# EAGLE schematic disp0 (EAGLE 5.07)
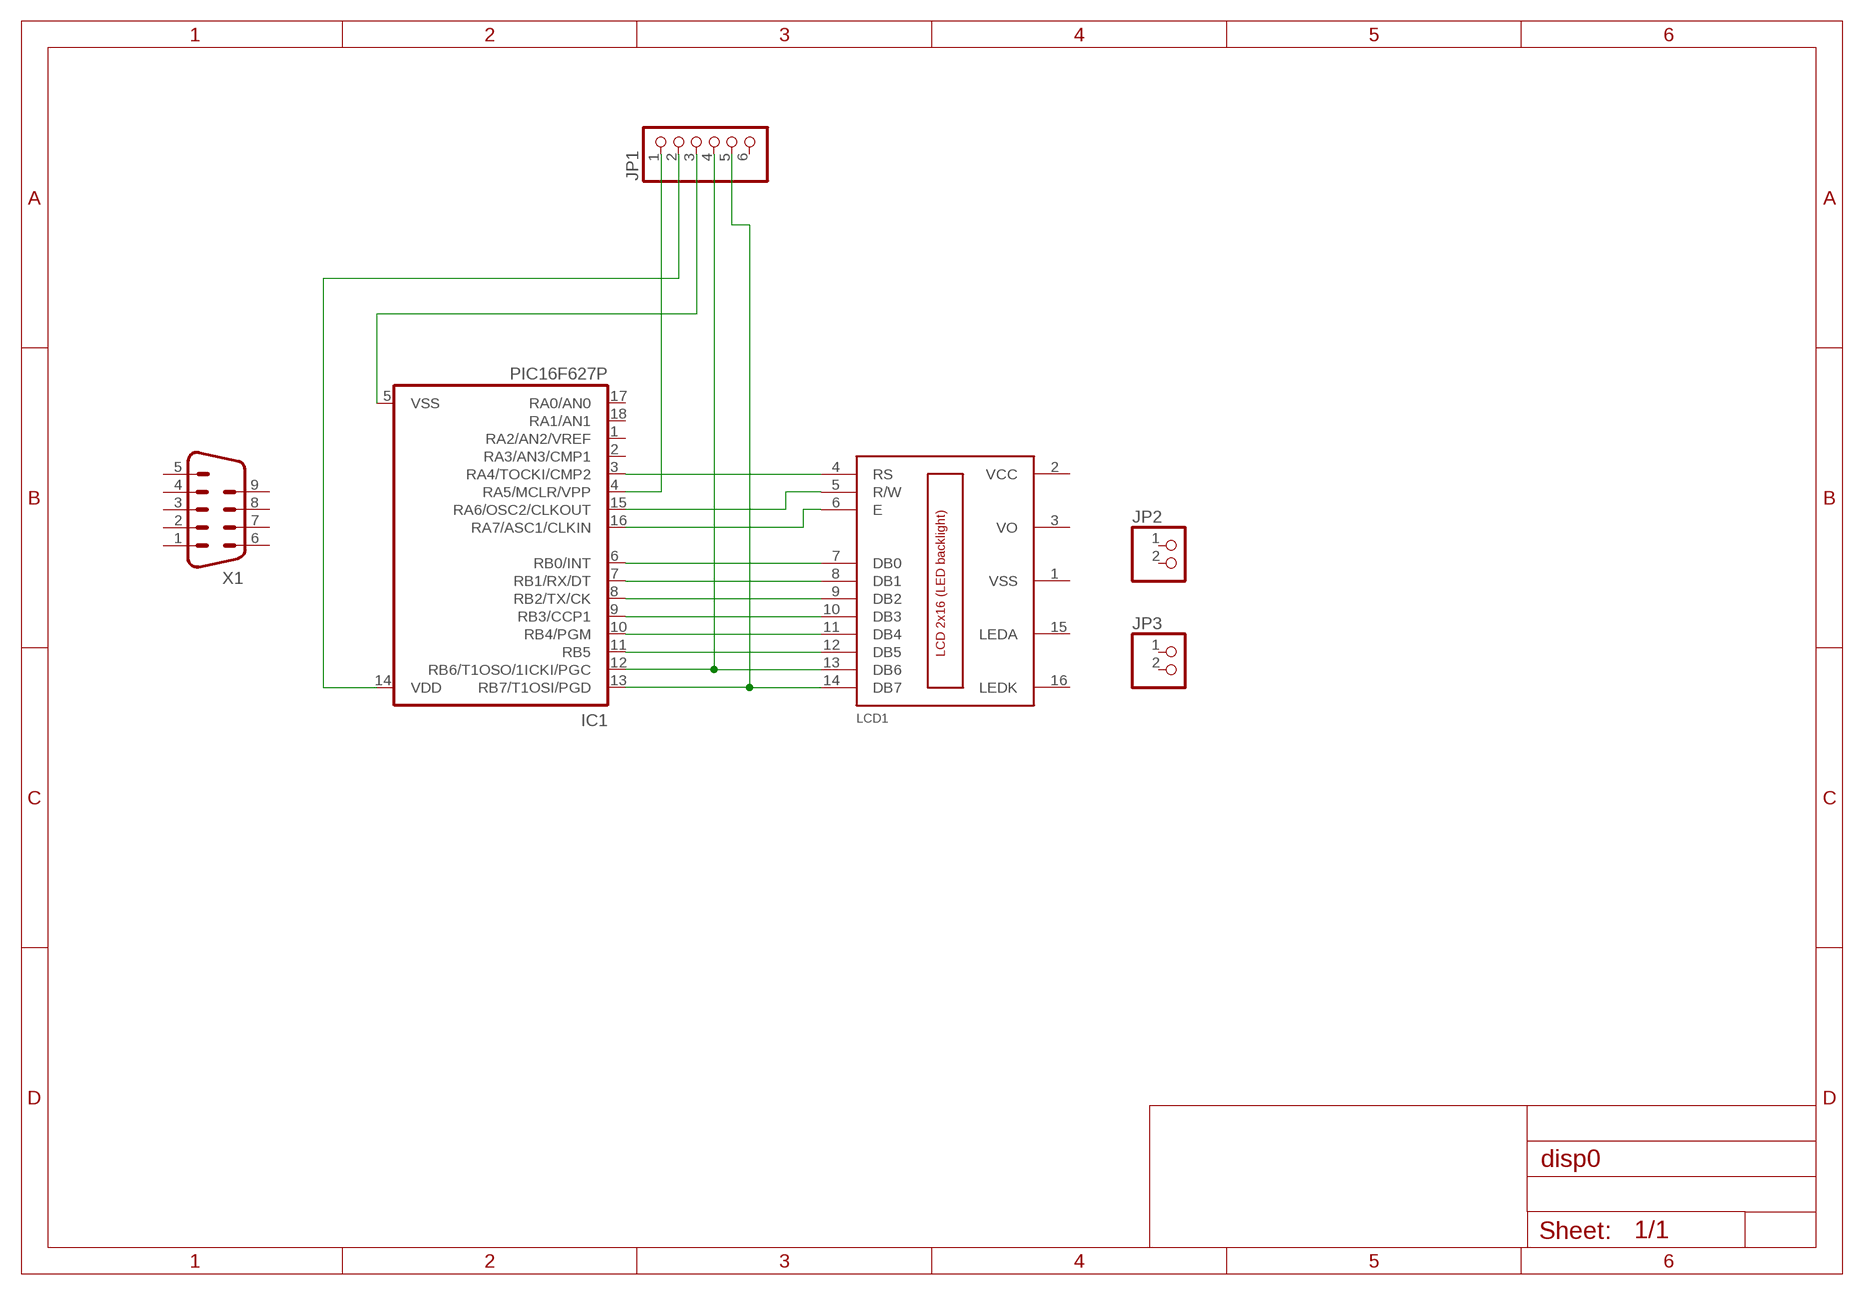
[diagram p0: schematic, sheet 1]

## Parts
IC1  PIC16F627P  [DIL18]
JP1  PINHD-1X6  [1X06]
JP2  PINHD-1X2  [1X02]
JP3  PINHD-1X2  [1X02]
LCD1  LCD_2X16  [HY-1602F]
X1  M09HP  [M09HP]

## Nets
N$1: IC1.4(RA5/MCLR/VPP) JP1.1
N$2: IC1.12(RB6/T1OSO/1ICKI/PGC) JP1.4 LCD1.13(DB6)
N$3: IC1.13(RB7/T1OSI/PGD) JP1.5 LCD1.14(DB7)
N$4: IC1.5(VSS) JP1.3
N$5: IC1.14(VDD) JP1.2
N$6: IC1.11(RB5) LCD1.12(DB5)
N$7: IC1.10(RB4/PGM) LCD1.11(DB4)
N$8: IC1.9(RB3/CCP1) LCD1.10(DB3)
N$9: IC1.8(RB2/TX/CK) LCD1.9(DB2)
N$10: IC1.7(RB1/RX/DT) LCD1.8(DB1)
N$11: IC1.6(RB0/INT) LCD1.7(DB0)
N$12: IC1.16(RA7/ASC1/CLKIN) LCD1.6(E)
N$13: IC1.15(RA6/OSC2/CLKOUT) LCD1.5(R/W)
N$14: IC1.3(RA4/TOCKI/CMP2) LCD1.4(RS)
Unconnected: IC1.1(RA2/AN2/VREF) IC1.2(RA3/AN3/CMP1) IC1.17(RA0/AN0) IC1.18(RA1/AN1) JP1.6 JP2.1 JP2.2 JP3.1 JP3.2 LCD1.3(VO) LCD1.15(LEDA) LCD1.16(LEDK) X1.1 X1.2 X1.3 X1.4 X1.5 X1.6 X1.7 X1.8 X1.9

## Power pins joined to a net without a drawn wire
VCC: LCD1.2(VCC)
VSS: LCD1.1(VSS)

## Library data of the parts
IC1 = microchip:PIC16*F62: FLASH-Based 8-Bit CMOS Microcontroller Source: http://ww1.microchip.com/downloads/en/DeviceDoc/40300C.pdf
JP1 = pinhead:PINHD-1X6: PIN HEADER
JP2 JP3 = pinhead:PINHD-1X2: PIN HEADER
LCD1 = lcd_2x16_led_backlight:LCD_2X16
X1 = con-subd:M09: SUB-D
